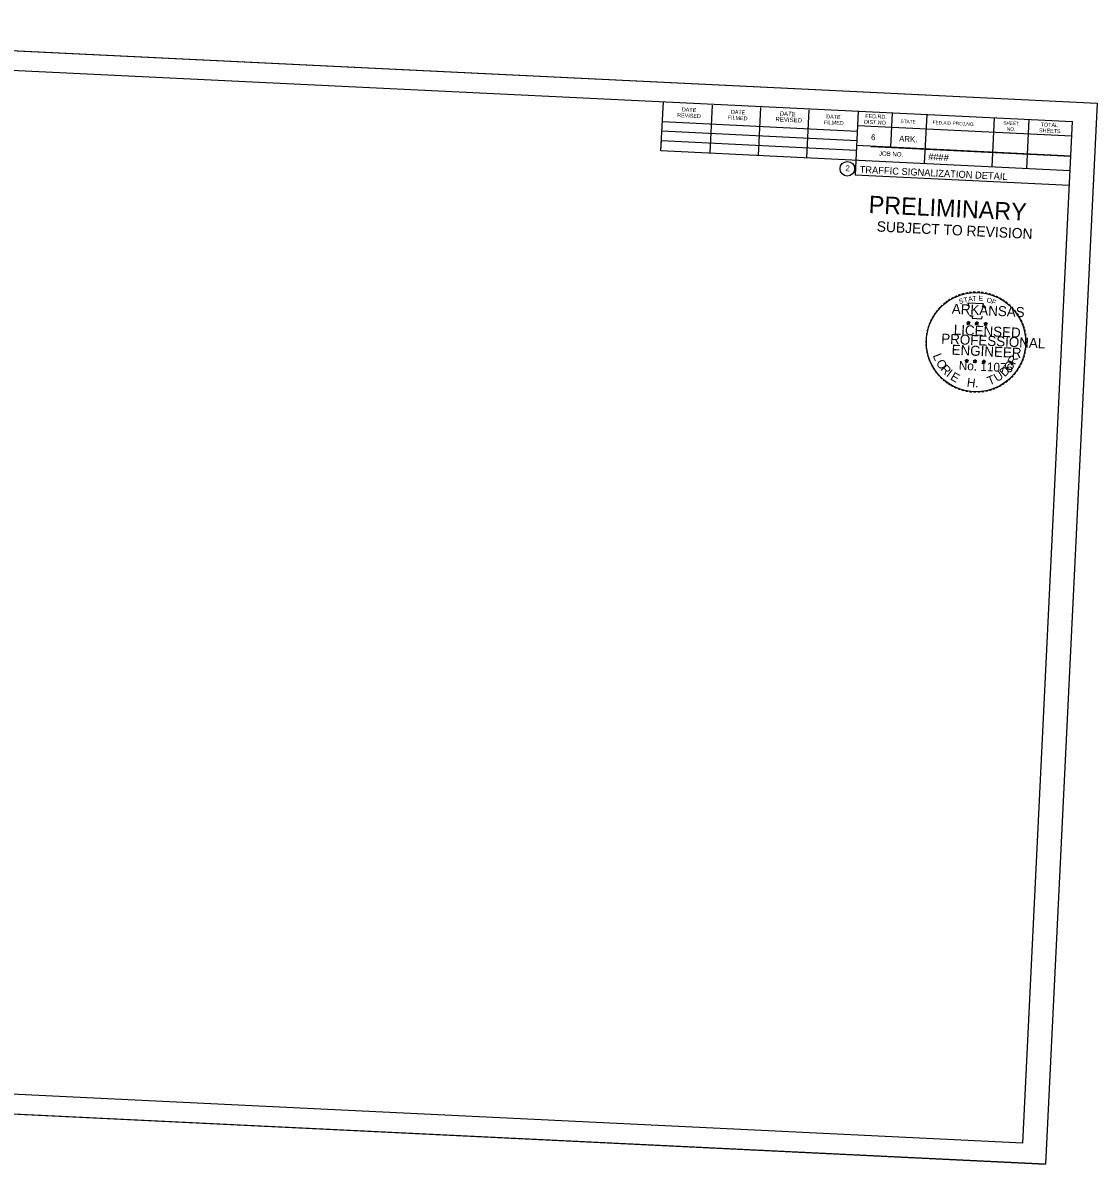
# Model space of a CAD drawing. Extents: x 661018 to 663325, y 642537 to 643074.
# Drawn here: x 662889 to 663325.1, y 642610.4 to 643073.9 of the extents above; entities that cross this region are included whole.
import ezdxf

# ---------------------------------------------------------------- set-up
doc = ezdxf.new("R2010")
doc.units = 0
doc.layers.add('R_Border Prem', color=7, linetype='Continuous')
doc.layers.add('R_No Plot', color=7, linetype='Continuous')

msp = doc.modelspace()

# ---------------------------------------------------------------- linework, layer by layer
at = {"layer": 'R_Border Prem'}
for p, q in [((663272.13, 642952.23), (663272.83, 642951.97)), ((663272.13, 642952.23), (663272.65, 642952.12)), ((663272.13, 642952.23), (663272.6, 642951.96)), ((663272.87, 642952.72), (663272.76, 642952.2)), ((663272.83, 642951.97), (663272.87, 642952.72)), ((663272.87, 642952.72), (663272.95, 642952.21)), ((663276.27, 642952.55), (663276.16, 642952.04)), ((663276.23, 642951.8), (663276.27, 642952.55)), ((663276.27, 642952.55), (663276.33, 642952.05)), ((663279.83, 642952.34), (663279.72, 642951.84)), ((663279.8, 642951.61), (663279.83, 642952.34)), ((663279.83, 642952.34), (663279.89, 642951.83)), ((663272.36, 642951.38), (663272.83, 642951.97)), ((663272.36, 642951.38), (663272.64, 642951.87)), ((663272.36, 642951.38), (663272.8, 642951.8)), ((663273.24, 642951.34), (663272.8, 642951.8)), ((663273.53, 642952.16), (663272.83, 642951.97)), ((663273.24, 642951.34), (663272.83, 642951.97)), ((663273.53, 642952.16), (663272.96, 642952.09)), ((663273.24, 642951.34), (663272.97, 642951.94)), ((663273.53, 642952.16), (663273.12, 642951.97)), ((663275.53, 642952.07), (663276.23, 642951.8)), ((663275.53, 642952.07), (663276.03, 642951.96)), ((663275.53, 642952.07), (663275.98, 642951.79)), ((663275.74, 642951.22), (663276.23, 642951.8)), ((663275.74, 642951.22), (663276.04, 642951.71)), ((663275.74, 642951.22), (663276.2, 642951.64)), ((663276.62, 642951.18), (663276.2, 642951.64)), ((663276.93, 642952), (663276.23, 642951.8)), ((663276.62, 642951.18), (663276.23, 642951.8)), ((663276.93, 642952), (663276.34, 642951.92)), ((663276.62, 642951.18), (663276.35, 642951.77)), ((663276.93, 642952), (663276.5, 642951.81)), ((663279.1, 642951.87), (663279.8, 642951.61)), ((663279.1, 642951.87), (663279.59, 642951.74)), ((663279.1, 642951.87), (663279.57, 642951.6)), ((663279.31, 642951.02), (663279.8, 642951.61)), ((663279.31, 642951.02), (663279.6, 642951.51)), ((663279.31, 642951.02), (663279.79, 642951.44)), ((663280.18, 642950.98), (663279.79, 642951.44)), ((663280.52, 642951.8), (663279.8, 642951.61)), ((663280.18, 642950.98), (663279.8, 642951.61)), ((663280.52, 642951.8), (663279.91, 642951.73)), ((663280.18, 642950.98), (663279.94, 642951.58)), ((663280.52, 642951.8), (663280.07, 642951.62)), ((663271.36, 642936.88), (663272.06, 642936.61)), ((663271.36, 642936.88), (663271.9, 642936.74)), ((663271.36, 642936.88), (663271.85, 642936.6)), ((663271.62, 642936.03), (663272.06, 642936.61)), ((663271.62, 642936.03), (663271.89, 642936.52)), ((663271.62, 642936.03), (663272.06, 642936.47)), ((663272.1, 642937.34), (663271.99, 642936.85)), ((663272.49, 642935.98), (663272.05, 642936.44)), ((663272.06, 642936.61), (663272.1, 642937.34)), ((663272.78, 642936.81), (663272.06, 642936.61)), ((663272.49, 642935.98), (663272.06, 642936.61)), ((663272.1, 642937.34), (663272.18, 642936.84)), ((663272.78, 642936.81), (663272.19, 642936.73)), ((663272.49, 642935.98), (663272.23, 642936.58)), ((663272.78, 642936.81), (663272.38, 642936.62)), ((663274.77, 642936.71), (663275.46, 642936.45)), ((663274.77, 642936.71), (663275.28, 642936.58)), ((663274.77, 642936.71), (663275.23, 642936.44)), ((663275, 642935.86), (663275.46, 642936.45)), ((663275, 642935.86), (663275.27, 642936.35)), ((663275, 642935.86), (663275.46, 642936.3)), ((663275.5, 642937.18), (663275.39, 642936.68)), ((663275.46, 642936.45), (663275.5, 642937.18)), ((663276.18, 642936.64), (663275.46, 642936.45)), ((663275.85, 642935.82), (663275.46, 642936.45)), ((663275.85, 642935.82), (663275.46, 642936.28)), ((663275.5, 642937.18), (663275.56, 642936.67)), ((663276.18, 642936.64), (663275.57, 642936.57)), ((663275.85, 642935.82), (663275.61, 642936.42)), ((663276.18, 642936.64), (663275.74, 642936.45)), ((663278.35, 642936.52), (663279.05, 642936.25)), ((663278.35, 642936.52), (663278.85, 642936.39)), ((663278.35, 642936.52), (663278.82, 642936.24)), ((663278.56, 642935.67), (663279.05, 642936.25)), ((663278.56, 642935.67), (663278.86, 642936.16)), ((663278.56, 642935.67), (663279.04, 642936.11)), ((663279.09, 642936.98), (663278.98, 642936.48)), ((663279.44, 642935.63), (663279.04, 642936.08)), ((663279.05, 642936.25), (663279.09, 642936.98)), ((663279.77, 642936.45), (663279.05, 642936.25)), ((663279.44, 642935.63), (663279.05, 642936.25)), ((663279.09, 642936.98), (663279.15, 642936.48)), ((663279.77, 642936.45), (663279.16, 642936.37)), ((663279.44, 642935.63), (663279.18, 642936.22)), ((663279.77, 642936.45), (663279.32, 642936.26))]:
    msp.add_line(p, q, dxfattribs=at)
for points in [[(663272.6, 642960.09), (663273.06, 642958.38)], [(663279.62, 642957.89), (663279.94, 642958.44), (663278.56, 642958.46), (663278.9, 642959.79), (663272.6, 642960.09)], [(663272.87, 642952.72), (663273.24, 642951.34), (663272.13, 642952.23), (663273.53, 642952.16), (663272.36, 642951.38), (663272.87, 642952.72)], [(663273.36, 642955.14), (663273.35, 642954.95), (663274.48, 642954.86), (663274.32, 642953.9), (663278.12, 642953.72), (663278.59, 642954.78)], [(663276.27, 642952.55), (663276.62, 642951.18), (663275.53, 642952.07), (663276.93, 642952), (663275.74, 642951.22), (663276.27, 642952.55)], [(663279.83, 642952.34), (663280.18, 642950.98), (663279.1, 642951.87), (663280.52, 642951.8), (663279.31, 642951.02), (663279.83, 642952.34)], [(663272.1, 642937.34), (663272.49, 642935.98), (663271.36, 642936.88), (663272.78, 642936.81), (663271.62, 642936.03), (663272.1, 642937.34)], [(663275.5, 642937.18), (663275.85, 642935.82), (663274.77, 642936.71), (663276.18, 642936.64), (663275, 642935.86), (663275.5, 642937.18)], [(663279.09, 642936.98), (663279.44, 642935.63), (663278.35, 642936.52), (663279.77, 642936.45), (663278.56, 642935.67), (663279.09, 642936.98)]]:
    msp.add_lwpolyline(points, dxfattribs=at)
for centre, radius in [((663275.89, 642944.21), 20.15), ((663272.81, 642951.96), 0.35), ((663272.81, 642951.96), 0.294), ((663272.81, 642951.96), 0.235), ((663272.81, 642951.96), 0.201), ((663272.81, 642951.96), 0.152), ((663272.81, 642951.96), 0.101), ((663272.81, 642951.96), 0.0602), ((663276.2, 642951.8), 0.35), ((663276.2, 642951.8), 0.294), ((663276.2, 642951.8), 0.235), ((663276.2, 642951.8), 0.201), ((663276.2, 642951.8), 0.152), ((663276.2, 642951.8), 0.101), ((663276.2, 642951.8), 0.0602), ((663279.77, 642951.6), 0.35), ((663279.77, 642951.6), 0.294), ((663279.77, 642951.6), 0.235), ((663279.77, 642951.6), 0.201), ((663279.77, 642951.6), 0.152), ((663279.77, 642951.6), 0.101), ((663279.77, 642951.6), 0.0602), ((663272.06, 642936.61), 0.35), ((663272.06, 642936.61), 0.294), ((663272.06, 642936.61), 0.235), ((663272.06, 642936.61), 0.201), ((663272.06, 642936.61), 0.152), ((663272.06, 642936.61), 0.101), ((663272.06, 642936.61), 0.0602), ((663275.44, 642936.44), 0.35), ((663275.44, 642936.44), 0.294), ((663275.44, 642936.44), 0.235), ((663275.44, 642936.44), 0.201), ((663275.44, 642936.44), 0.152), ((663275.44, 642936.44), 0.101), ((663275.44, 642936.44), 0.0602), ((663279.02, 642936.25), 0.35), ((663279.02, 642936.25), 0.294), ((663279.02, 642936.25), 0.235), ((663279.02, 642936.25), 0.201), ((663279.02, 642936.25), 0.152), ((663279.02, 642936.25), 0.101), ((663279.02, 642936.25), 0.0602)]:
    msp.add_circle(centre, radius, dxfattribs=at)
at = {"layer": 'R_No Plot'}
for p, q in [((662652.01, 643073.86), (663325.06, 643041.18)), ((662676.66, 643064.78), (663315.08, 643033.78)), ((662984.6, 643049.3), (662984.6, 643049.3)), ((662984.6, 643049.3), (662984.6, 643049.3)), ((663148.02, 643021.9), (663148.99, 643041.85)), ((663167.93, 643020.93), (663168.88, 643040.48)), ((663187.63, 643019.97), (663188.58, 643039.52)), ((663207.18, 643019.02), (663208.13, 643038.57)), ((663228.06, 643038.01), (663226.8, 643012.16)), ((663241.87, 643037.34), (663241.19, 643023.32)), ((663255.88, 643036.65), (663254.91, 643016.71)), ((663148.59, 643033.73), (663227.66, 643029.89)), ((663314.8, 643027.84), (663227.77, 643032.07)), ((663283.3, 643035.32), (663282.33, 643015.37)), ((663294.94, 642618.92), (663315.08, 643033.78)), ((663297.32, 643034.64), (663296.35, 643014.69)), ((663148.41, 643029.97), (663227.48, 643026.13)), ((663314.8, 643027.88), (663314.8, 643027.88)), ((663148.02, 643021.9), (663148.22, 643026.06)), ((663314.12, 643013.83), (663148.02, 643021.9)), ((663148.22, 643026.06), (663227.29, 643022.22)), ((663314.4, 643019.77), (663227.38, 643023.99)), ((663233.35, 643023.7), (663314.4, 643019.77)), ((663226.8, 643012.16), (663313.83, 643007.93)), ((663294.94, 642618.92), (662656.52, 642649.92)), ((662631.09, 642643.11), (663304.15, 642610.42))]:
    msp.add_line(p, q, dxfattribs=at)
msp.add_lwpolyline([(662651.99, 643073.86), (663325.06, 643041.18), (663304.14, 642610.41), (662631.07, 642643.1)], close=True, dxfattribs=at)
msp.add_circle((663223.66, 643014.61), 2.96, dxfattribs=at)

# ---------------------------------------------------------------- texts
at = {"layer": 'R_Border Prem'}
for s, height, rotation, p in [('PRELIMINARY', 7.0754, 357.2199, (663232.22, 642996.64)), ('SUBJECT TO REVISION', 4.1949, 357.2199, (663235.52, 642989.14)), ('-', 3.25, 33.4517, (663265.06, 642960.02)), ('-', 3.25, 31.2835, (663266.29, 642960.75)), ('-', 3.25, 26.0117, (663267.54, 642961.45)), ('-', 3.25, 21.5271, (663268.84, 642962.03)), ('S', 2.03, 18.8139, (663269.23, 642959.61)), ('-', 3.25, 16.396, (663270.18, 642962.51)), ('T', 2.03, 13.6235, (663271.12, 642960.19)), ('-', 3.25, 10.8501, (663271.73, 642962.92)), ('A', 2.03, 8.4331, (663272.81, 642960.61)), ('-', 3.25, 7.4393, (663273.1, 642963.18)), ('T', 2.03, 3.2427, (663274.54, 642960.88)), ('-', 3.25, 3.1167, (663274.59, 642963.32)), ('-', 3.25, 357.4061, (663276.17, 642963.39)), ('E', 2.03, 358.0523, (663276.8, 642961)), ('-', 3.25, 354.963, (663277.63, 642963.3)), ('-', 3.25, 349.3816, (663279.12, 642963.1)), ('O', 2.03, 347.6714, (663280.04, 642960.4)), ('-', 3.25, 344.4248, (663280.57, 642962.82)), ('F', 2.03, 337.2906, (663281.95, 642959.85)), ('-', 3.25, 339.5561, (663281.87, 642962.42)), ('-', 3.25, 335.075, (663283.31, 642961.91)), ('-', 3.25, 331.341, (663284.58, 642961.31)), ('-', 3.25, 326.8608, (663285.72, 642960.67)), ('-', 3.25, 51.4524, (663260.45, 642955.5)), ('-', 3.25, 47.8341, (663261.32, 642956.62)), ('-', 3.25, 45.643, (663262.2, 642957.54)), ('-', 3.25, 40.1822, (663263.17, 642958.48)), ('-', 3.25, 36.1706, (663264.09, 642959.29)), ('ARKANSAS', 4.061, 357.2199, (663265.99, 642955.75)), ('-', 3.25, 323.0826, (663286.97, 642959.88)), ('-', 3.25, 317.7496, (663288.19, 642958.96)), ('-', 3.25, 312.7985, (663289.35, 642957.9)), ('-', 3.25, 307.0996, (663290.44, 642956.72)), ('-', 3.25, 69.6144, (663257.96, 642950.79)), ('-', 3.25, 64.9942, (663258.44, 642952.04)), ('-', 3.25, 60.0913, (663259.03, 642953.24)), ('-', 3.25, 55.2906, (663259.73, 642954.46)), ('-', 3.25, 303.8721, (663291.47, 642955.45)), ('-', 2.84, 300.8952, (663292.37, 642954.26)), ('-', 3.25, 296.8883, (663292.98, 642952.98)), ('-', 3.25, 82.4063, (663256.92, 642946.53)), ('-', 3.25, 78.4212, (663257.16, 642947.92)), ('-', 3.25, 72.6809, (663257.48, 642949.35)), ('PROFESSIONAL', 4.0609, 357.2199, (663261.7, 642943.66)), ('LICENSED', 4.061, 357.2199, (663266.79, 642947.28)), ('-', 3.25, 291.8827, (663293.58, 642951.71)), ('-', 3.25, 287.7927, (663294.03, 642950.54)), ('-', 3.25, 282.3432, (663294.45, 642949.33)), ('-', 3.25, 277.7693, (663294.79, 642947.78)), ('-', 3.25, 96.1678, (663256.88, 642942.28)), ('-', 3.25, 91.4158, (663256.8, 642943.63)), ('-', 3.25, 86.2822, (663256.81, 642945.11)), ('ENGINEER', 4.061, 357.2199, (663265.91, 642939.13)), ('-', 3.25, 267.1606, (663295.09, 642943.46)), ('-', 3.25, 273.8161, (663295.03, 642946.25)), ('-', 3.25, 271.55, (663295.09, 642944.76)), ('-', 3.25, 98.9349, (663257.08, 642940.77)), ('-', 3.25, 102.6778, (663257.36, 642939.54)), ('-', 3.25, 106.3073, (663257.71, 642938.25)), ('L', 3.57, 292.0744, (663258.28, 642938.76)), ('R', 3.57, 63.9331, (663291.7, 642934.73)), ('-', 3.25, 252.9825, (663294.49, 642939.43)), ('-', 3.25, 258.2152, (663294.77, 642940.8)), ('-', 3.25, 260.7371, (663294.98, 642942.13)), ('-', 3.25, 111.2842, (663258.17, 642937.01)), ('-', 3.25, 112.9488, (663258.74, 642935.73)), ('-', 3.25, 117.667, (663259.41, 642934.51)), ('-', 3.25, 123.1134, (663260.15, 642933.34)), ('O', 3.57, 301.8803, (663259.47, 642935.84)), ('R', 3.57, 312.0368, (663261.2, 642933.08)), ('No. 11076', 3.567, 357.2199, (663268.84, 642933)), ('D', 3.57, 43.7954, (663287.46, 642929.87)), ('O', 3.57, 53.7766, (663289.78, 642932.09)), ('-', 3.25, 241.8396, (663292.94, 642935.41)), ('-', 3.25, 245.1086, (663293.54, 642936.66)), ('-', 3.25, 250.088, (663294.05, 642937.99)), ('-', 3.25, 127.938, (663261.05, 642932.15)), ('-', 3.25, 131.4437, (663262.04, 642931.01)), ('-', 3.25, 136.1537, (663263.06, 642930.02)), ('-', 3.25, 141.8663, (663264.15, 642929.13)), ('I', 3.57, 322.7191, (663263.52, 642930.55)), ('E', 3.57, 329.3699, (663265.18, 642929.21)), ('H', 3.57, 352.7502, (663272.01, 642926.19)), ('T', 3.57, 21.905, (663281.28, 642926.58)), ('U', 3.57, 32.5873, (663284.46, 642927.89)), ('-', 3.25, 222.9853, (663289.23, 642930.44)), ('-', 3.25, 228.4737, (663290.26, 642931.52)), ('-', 3.25, 231.0652, (663291.19, 642932.65)), ('-', 3.25, 236.2912, (663292.07, 642933.92)), ('-', 3.25, 145.3097, (663265.24, 642928.33)), ('-', 3.25, 148.7903, (663266.38, 642927.6)), ('-', 3.25, 151.8201, (663267.44, 642927.07)), ('-', 3.25, 155.7811, (663268.66, 642926.49)), ('-', 3.25, 160.0182, (663270.04, 642925.98)), ('-', 3.25, 164.7754, (663271.47, 642925.6)), ('-', 3.25, 170.3354, (663273.02, 642925.29)), ('.', 3.57, 3.7831, (663275.53, 642925.78)), ('-', 3.25, 192.6942, (663280.71, 642925.67)), ('-', 3.25, 197.9383, (663282.11, 642926.08)), ('-', 3.25, 201.4715, (663283.39, 642926.57)), ('-', 3.25, 204.5768, (663284.68, 642927.17)), ('-', 3.25, 209.469, (663285.86, 642927.83)), ('-', 3.25, 212.9563, (663286.96, 642928.57)), ('-', 3.25, 218.305, (663288.13, 642929.45)), ('-', 3.25, 173.7382, (663274.54, 642925.09)), ('-', 3.25, 178.8117, (663276.06, 642925.06)), ('-', 3.25, 183.0366, (663277.7, 642925.15)), ('-', 3.25, 188.5057, (663279.21, 642925.33))]:
    msp.add_text(s, height=height, rotation=rotation, dxfattribs=at).set_placement(p)
at = {"layer": 'R_No Plot'}
for s, height, p in [('REVISED', 1.581, (663154.6, 643035.62)), ('DATE', 1.581, (663156.49, 643037.92)), ('FILMED', 1.581, (663175.11, 643034.63)), ('DATE', 1.581, (663176.4, 643036.95)), ('REVISED', 1.777, (663194.46, 643033.89)), ('DATE', 1.777, (663196.15, 643036.2)), ('DATE', 1.581, (663215.08, 643035.07)), ('FED.RD.', 1.581, (663230.92, 643035.28)), ('FILMED', 1.581, (663214.16, 643032.73)), ('DIST.NO.', 1.581, (663230.4, 643032.91)), ('STATE', 1.383, (663245.23, 643033.21)), ('FED.AID PROJ.NO.', 1.3827, (663258.28, 643032.77)), ('SHEET', 1.383, (663286.93, 643032.56)), ('NO.', 1.383, (663288.39, 643030.1)), ('SHEETS', 1.581, (663301.44, 643029.46)), ('TOTAL', 1.581, (663302.12, 643031.82)), ('6', 2.37, (663233.24, 643026.26)), ('ARK.', 2.37, (663244.66, 643025.7)), ('JOB NO.', 1.777, (663236.49, 643019.99)), ('####', 2.83, (663256.39, 643018.13)), ('2', 2.37, (663222.84, 643013.67)), ('TRAFFIC SIGNALIZATION DETAIL ', 2.8302, (663228.59, 643012.94))]:
    msp.add_text(s, height=height, rotation=357.2199, dxfattribs=at).set_placement(p)

doc.saveas('drawing.dxf')
